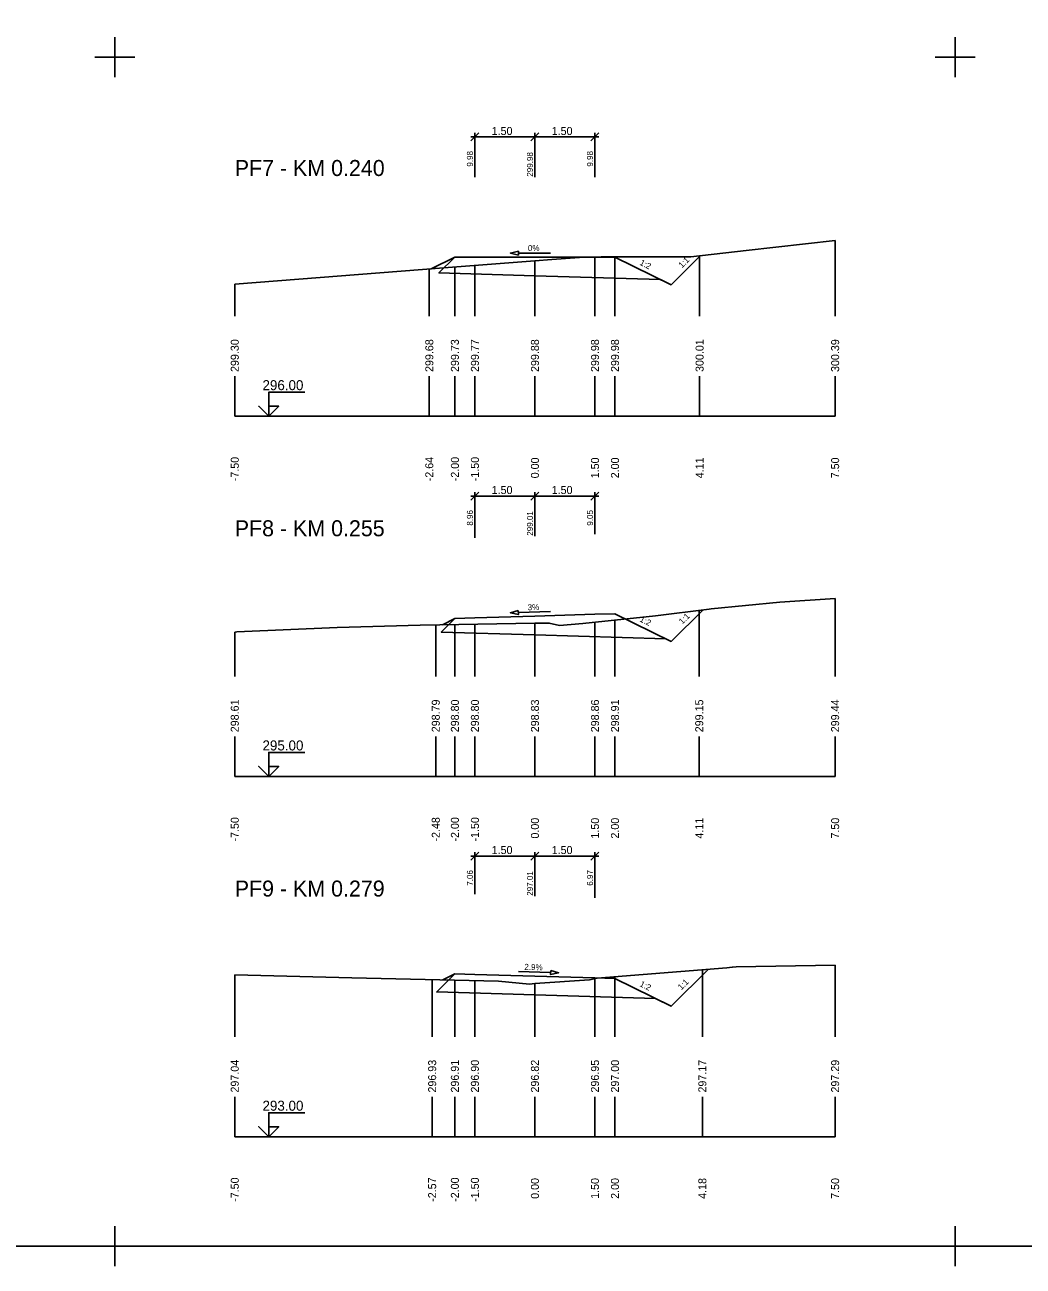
# Model space of a CAD drawing. Extents: x -5 to 1265, y -2 to 602.
# Drawn here: x 397.5 to 647, y -2.3 to 307.8 of the extents above; entities that cross this region are included whole.
import ezdxf

# ---------------------------------------------------------------- set-up
doc = ezdxf.new("R2010")
doc.units = 0
for name, color, linetype in [('KOTA', 7, 'Continuous'), ('KOTA_DELKY', 7, 'Continuous'), ('KOTA_DELKY_CONT', 7, 'Continuous'), ('NS_TELESO_VOZOVKY', 7, 'Continuous'), ('NS_V_PF', 7, 'Continuous'), ('REZY_PF_PUVODNI', 7, 'Continuous'), ('SESTAVY_REZU_PF', 7, 'Continuous'), ('SKLON', 7, 'Continuous'), ('SVK', 7, 'Continuous')]:
    doc.layers.add(name, color=color, linetype=linetype)

msp = doc.modelspace()

# ---------------------------------------------------------------- linework, layer by layer
for p, q in [((420, 304.67), (420, 294.67)), ((420, 304.67), (420, 294.67)), ((420, 304.67), (420, 294.67)), ((420, 304.67), (420, 294.67)), ((420, 304.67), (420, 294.67)), ((420, 304.67), (420, 294.67)), ((420, 304.67), (420, 294.67)), ((420, 304.67), (420, 294.67)), ((420, 304.67), (420, 294.67)), ((420, 304.67), (420, 294.67)), ((420, 304.67), (420, 294.67)), ((420, 304.67), (420, 294.67)), ((420, 304.67), (420, 294.67)), ((420, 304.67), (420, 294.67)), ((420, 304.67), (420, 294.67)), ((420, 304.67), (420, 294.67)), ((420, 304.67), (420, 294.67)), ((420, 304.67), (420, 294.67)), ((420, 304.67), (420, 294.67)), ((420, 304.67), (420, 294.67)), ((420, 304.67), (420, 294.67)), ((420, 304.67), (420, 294.67)), ((420, 304.67), (420, 294.67)), ((420, 304.67), (420, 294.67)), ((420, 304.67), (420, 294.67)), ((420, 304.67), (420, 294.67)), ((420, 304.67), (420, 294.67)), ((420, 304.67), (420, 294.67)), ((420, 304.67), (420, 294.67)), ((420, 304.67), (420, 294.67)), ((420, 304.67), (420, 294.67)), ((420, 304.67), (420, 294.67)), ((420, 304.67), (420, 294.67)), ((420, 304.67), (420, 294.67)), ((420, 304.67), (420, 294.67)), ((420, 304.67), (420, 294.67)), ((420, 304.67), (420, 294.67)), ((420, 304.67), (420, 294.67)), ((420, 304.67), (420, 294.67)), ((420, 304.67), (420, 294.67)), ((420, 304.67), (420, 294.67)), ((420, 304.67), (420, 294.67)), ((420, 304.67), (420, 294.67)), ((420, 304.67), (420, 294.67)), ((420, 304.67), (420, 294.67)), ((420, 304.67), (420, 294.67)), ((420, 304.67), (420, 294.67)), ((420, 304.67), (420, 294.67)), ((420, 304.67), (420, 294.67)), ((420, 304.67), (420, 294.67)), ((420, 304.67), (420, 294.67)), ((420, 304.67), (420, 294.67)), ((420, 304.67), (420, 294.67)), ((420, 304.67), (420, 294.67)), ((420, 304.67), (420, 294.67)), ((420, 304.67), (420, 294.67)), ((420, 304.67), (420, 294.67)), ((420, 304.67), (420, 294.67)), ((420, 304.67), (420, 294.67)), ((420, 304.67), (420, 294.67)), ((420, 304.67), (420, 294.67)), ((420, 304.67), (420, 294.67)), ((420, 304.67), (420, 294.67)), ((420, 304.67), (420, 294.67)), ((420, 304.67), (420, 294.67)), ((420, 304.67), (420, 294.67)), ((630, 304.67), (630, 294.67)), ((630, 304.67), (630, 294.67)), ((630, 304.67), (630, 294.67)), ((630, 304.67), (630, 294.67)), ((630, 304.67), (630, 294.67)), ((630, 304.67), (630, 294.67)), ((630, 304.67), (630, 294.67)), ((630, 304.67), (630, 294.67)), ((630, 304.67), (630, 294.67)), ((630, 304.67), (630, 294.67)), ((630, 304.67), (630, 294.67)), ((630, 304.67), (630, 294.67)), ((630, 304.67), (630, 294.67)), ((630, 304.67), (630, 294.67)), ((630, 304.67), (630, 294.67)), ((630, 304.67), (630, 294.67)), ((630, 304.67), (630, 294.67)), ((630, 304.67), (630, 294.67)), ((630, 304.67), (630, 294.67)), ((630, 304.67), (630, 294.67)), ((630, 304.67), (630, 294.67)), ((630, 304.67), (630, 294.67)), ((630, 304.67), (630, 294.67)), ((630, 304.67), (630, 294.67)), ((630, 304.67), (630, 294.67)), ((630, 304.67), (630, 294.67)), ((630, 304.67), (630, 294.67)), ((630, 304.67), (630, 294.67)), ((630, 304.67), (630, 294.67)), ((630, 304.67), (630, 294.67)), ((630, 304.67), (630, 294.67)), ((630, 304.67), (630, 294.67)), ((630, 304.67), (630, 294.67)), ((630, 304.67), (630, 294.67)), ((630, 304.67), (630, 294.67)), ((630, 304.67), (630, 294.67)), ((630, 304.67), (630, 294.67)), ((630, 304.67), (630, 294.67)), ((630, 304.67), (630, 294.67)), ((630, 304.67), (630, 294.67)), ((630, 304.67), (630, 294.67)), ((630, 304.67), (630, 294.67)), ((630, 304.67), (630, 294.67)), ((630, 304.67), (630, 294.67)), ((630, 304.67), (630, 294.67)), ((630, 304.67), (630, 294.67)), ((630, 304.67), (630, 294.67)), ((630, 304.67), (630, 294.67)), ((630, 304.67), (630, 294.67)), ((630, 304.67), (630, 294.67)), ((630, 304.67), (630, 294.67)), ((630, 304.67), (630, 294.67)), ((630, 304.67), (630, 294.67)), ((630, 304.67), (630, 294.67)), ((630, 304.67), (630, 294.67)), ((630, 304.67), (630, 294.67)), ((630, 304.67), (630, 294.67)), ((630, 304.67), (630, 294.67)), ((630, 304.67), (630, 294.67)), ((630, 304.67), (630, 294.67)), ((630, 304.67), (630, 294.67)), ((630, 304.67), (630, 294.67)), ((630, 304.67), (630, 294.67)), ((630, 304.67), (630, 294.67)), ((630, 304.67), (630, 294.67)), ((630, 304.67), (630, 294.67)), ((425, 299.67), (415, 299.67)), ((425, 299.67), (415, 299.67)), ((425, 299.67), (415, 299.67)), ((425, 299.67), (415, 299.67)), ((425, 299.67), (415, 299.67)), ((425, 299.67), (415, 299.67)), ((425, 299.67), (415, 299.67)), ((425, 299.67), (415, 299.67)), ((425, 299.67), (415, 299.67)), ((425, 299.67), (415, 299.67)), ((425, 299.67), (415, 299.67)), ((425, 299.67), (415, 299.67)), ((425, 299.67), (415, 299.67)), ((425, 299.67), (415, 299.67)), ((425, 299.67), (415, 299.67)), ((425, 299.67), (415, 299.67)), ((425, 299.67), (415, 299.67)), ((425, 299.67), (415, 299.67)), ((425, 299.67), (415, 299.67)), ((425, 299.67), (415, 299.67)), ((425, 299.67), (415, 299.67)), ((425, 299.67), (415, 299.67)), ((425, 299.67), (415, 299.67)), ((425, 299.67), (415, 299.67)), ((425, 299.67), (415, 299.67)), ((425, 299.67), (415, 299.67)), ((425, 299.67), (415, 299.67)), ((425, 299.67), (415, 299.67)), ((425, 299.67), (415, 299.67)), ((425, 299.67), (415, 299.67)), ((425, 299.67), (415, 299.67)), ((425, 299.67), (415, 299.67)), ((425, 299.67), (415, 299.67)), ((425, 299.67), (415, 299.67)), ((425, 299.67), (415, 299.67)), ((425, 299.67), (415, 299.67)), ((425, 299.67), (415, 299.67)), ((425, 299.67), (415, 299.67)), ((425, 299.67), (415, 299.67)), ((425, 299.67), (415, 299.67)), ((425, 299.67), (415, 299.67)), ((425, 299.67), (415, 299.67)), ((425, 299.67), (415, 299.67)), ((425, 299.67), (415, 299.67)), ((425, 299.67), (415, 299.67)), ((425, 299.67), (415, 299.67)), ((425, 299.67), (415, 299.67)), ((425, 299.67), (415, 299.67)), ((425, 299.67), (415, 299.67)), ((425, 299.67), (415, 299.67)), ((425, 299.67), (415, 299.67)), ((425, 299.67), (415, 299.67)), ((425, 299.67), (415, 299.67)), ((425, 299.67), (415, 299.67)), ((425, 299.67), (415, 299.67)), ((425, 299.67), (415, 299.67)), ((425, 299.67), (415, 299.67)), ((425, 299.67), (415, 299.67)), ((425, 299.67), (415, 299.67)), ((425, 299.67), (415, 299.67)), ((425, 299.67), (415, 299.67)), ((425, 299.67), (415, 299.67)), ((425, 299.67), (415, 299.67)), ((425, 299.67), (415, 299.67)), ((425, 299.67), (415, 299.67)), ((425, 299.67), (415, 299.67)), ((635, 299.67), (625, 299.67)), ((635, 299.67), (625, 299.67)), ((635, 299.67), (625, 299.67)), ((635, 299.67), (625, 299.67)), ((635, 299.67), (625, 299.67)), ((635, 299.67), (625, 299.67)), ((635, 299.67), (625, 299.67)), ((635, 299.67), (625, 299.67)), ((635, 299.67), (625, 299.67)), ((635, 299.67), (625, 299.67)), ((635, 299.67), (625, 299.67)), ((635, 299.67), (625, 299.67)), ((635, 299.67), (625, 299.67)), ((635, 299.67), (625, 299.67)), ((635, 299.67), (625, 299.67)), ((635, 299.67), (625, 299.67)), ((635, 299.67), (625, 299.67)), ((635, 299.67), (625, 299.67)), ((635, 299.67), (625, 299.67)), ((635, 299.67), (625, 299.67)), ((635, 299.67), (625, 299.67)), ((635, 299.67), (625, 299.67)), ((635, 299.67), (625, 299.67)), ((635, 299.67), (625, 299.67)), ((635, 299.67), (625, 299.67)), ((635, 299.67), (625, 299.67)), ((635, 299.67), (625, 299.67)), ((635, 299.67), (625, 299.67)), ((635, 299.67), (625, 299.67)), ((635, 299.67), (625, 299.67)), ((635, 299.67), (625, 299.67)), ((635, 299.67), (625, 299.67)), ((635, 299.67), (625, 299.67)), ((635, 299.67), (625, 299.67)), ((635, 299.67), (625, 299.67)), ((635, 299.67), (625, 299.67)), ((635, 299.67), (625, 299.67)), ((635, 299.67), (625, 299.67)), ((635, 299.67), (625, 299.67)), ((635, 299.67), (625, 299.67)), ((635, 299.67), (625, 299.67)), ((635, 299.67), (625, 299.67)), ((635, 299.67), (625, 299.67)), ((635, 299.67), (625, 299.67)), ((635, 299.67), (625, 299.67)), ((635, 299.67), (625, 299.67)), ((635, 299.67), (625, 299.67)), ((635, 299.67), (625, 299.67)), ((635, 299.67), (625, 299.67)), ((635, 299.67), (625, 299.67)), ((635, 299.67), (625, 299.67)), ((635, 299.67), (625, 299.67)), ((635, 299.67), (625, 299.67)), ((635, 299.67), (625, 299.67)), ((635, 299.67), (625, 299.67)), ((635, 299.67), (625, 299.67)), ((635, 299.67), (625, 299.67)), ((635, 299.67), (625, 299.67)), ((635, 299.67), (625, 299.67)), ((635, 299.67), (625, 299.67)), ((635, 299.67), (625, 299.67)), ((635, 299.67), (625, 299.67)), ((635, 299.67), (625, 299.67)), ((635, 299.67), (625, 299.67)), ((635, 299.67), (625, 299.67)), ((635, 299.67), (625, 299.67)), ((420, 7.67), (420, -2.33)), ((420, 7.67), (420, -2.33)), ((420, 7.67), (420, -2.33)), ((420, 7.67), (420, -2.33)), ((420, 7.67), (420, -2.33)), ((420, 7.67), (420, -2.33)), ((420, 7.67), (420, -2.33)), ((420, 7.67), (420, -2.33)), ((420, 7.67), (420, -2.33)), ((420, 7.67), (420, -2.33)), ((420, 7.67), (420, -2.33)), ((420, 7.67), (420, -2.33)), ((630, 7.67), (630, -2.33)), ((630, 7.67), (630, -2.33)), ((630, 7.67), (630, -2.33)), ((630, 7.67), (630, -2.33)), ((630, 7.67), (630, -2.33)), ((630, 7.67), (630, -2.33)), ((630, 7.67), (630, -2.33)), ((630, 7.67), (630, -2.33)), ((630, 7.67), (630, -2.33)), ((630, 7.67), (630, -2.33)), ((630, 7.67), (630, -2.33)), ((630, 7.67), (630, -2.33)), ((425, 2.67), (415, 2.67)), ((425, 2.67), (415, 2.67)), ((425, 2.67), (415, 2.67)), ((425, 2.67), (415, 2.67)), ((425, 2.67), (415, 2.67)), ((425, 2.67), (415, 2.67)), ((425, 2.67), (415, 2.67)), ((425, 2.67), (415, 2.67)), ((425, 2.67), (415, 2.67)), ((425, 2.67), (415, 2.67)), ((425, 2.67), (415, 2.67)), ((425, 2.67), (415, 2.67)), ((635, 2.67), (625, 2.67)), ((635, 2.67), (625, 2.67)), ((635, 2.67), (625, 2.67)), ((635, 2.67), (625, 2.67)), ((635, 2.67), (625, 2.67)), ((635, 2.67), (625, 2.67)), ((635, 2.67), (625, 2.67)), ((635, 2.67), (625, 2.67)), ((635, 2.67), (625, 2.67)), ((635, 2.67), (625, 2.67)), ((635, 2.67), (625, 2.67)), ((635, 2.67), (625, 2.67))]:
    msp.add_line(p, q)
msp.add_lwpolyline([(0, 596.67), (1260, 596.67), (1260, 2.67), (0, 2.67)], close=True)
at = {"layer": 'KOTA'}
for points in [[(458.51, 210), (456.01, 212.5), (458.51, 210), (458.51, 216), (467.51, 216)], [(458.51, 210), (461.01, 212.5), (458.51, 212.5), (458.51, 210)], [(458.51, 210), (461.01, 212.5), (458.51, 212.5)], [(458.51, 120), (456.01, 122.5), (458.51, 120), (458.51, 126), (467.51, 126)], [(458.51, 120), (461.01, 122.5), (458.51, 122.5), (458.51, 120)], [(458.51, 120), (461.01, 122.5), (458.51, 122.5)], [(458.51, 30), (456.01, 32.5), (458.51, 30), (458.51, 36), (467.51, 36)], [(458.51, 30), (461.01, 32.5), (458.51, 32.5), (458.51, 30)], [(458.51, 30), (461.01, 32.5), (458.51, 32.5)]]:
    msp.add_lwpolyline(points, dxfattribs=at)
at = {"layer": 'KOTA_DELKY'}
for points in [[(509, 278.75), (511, 280.75)], [(509, 279.75), (526, 279.75)], [(510, 269.75), (510, 280.75)], [(524, 278.75), (526, 280.75)], [(524, 278.75), (526, 280.75)], [(524, 279.75), (541, 279.75)], [(525, 269.75), (525, 280.75)], [(525, 269.75), (525, 280.75)], [(539, 278.75), (541, 280.75)], [(540, 269.75), (540, 280.75)], [(509, 189.06), (511, 191.06)], [(509, 190.06), (526, 190.06)], [(510, 179.61), (510, 191.06)], [(524, 189.06), (526, 191.06)], [(524, 189.06), (526, 191.06)], [(524, 190.06), (541, 190.06)], [(525, 180.06), (525, 191.06)], [(525, 180.06), (525, 191.06)], [(539, 189.06), (541, 191.06)], [(540, 180.51), (540, 191.06)], [(509, 99.12), (511, 101.12)], [(509, 100.12), (526, 100.12)], [(510, 90.57), (510, 101.12)], [(524, 99.12), (526, 101.12)], [(524, 99.12), (526, 101.12)], [(524, 100.12), (541, 100.12)], [(525, 90.12), (525, 101.12)], [(525, 90.12), (525, 101.12)], [(539, 99.12), (541, 101.12)], [(540, 89.68), (540, 101.12)]]:
    msp.add_lwpolyline(points, dxfattribs=at)
at = {"layer": 'NS_TELESO_VOZOVKY'}
for points in [[(525, 249.75), (540, 249.75), (545, 249.75), (559.01, 242.82), (556.41, 244.11), (525, 245.05), (501.02, 245.77), (505, 249.75), (510, 249.75), (525, 249.75)], [(525, 160.06), (540, 160.51), (545, 160.66), (559.01, 153.73), (557.7, 154.38), (525, 155.36), (501.6, 156.06), (505, 159.46), (510, 159.61), (525, 160.06)], [(525, 70.12), (540, 69.68), (545, 69.54), (559.01, 62.61), (555.14, 64.52), (525, 65.42), (500.45, 66.16), (505, 70.71), (510, 70.57), (525, 70.12)]]:
    msp.add_lwpolyline(points, dxfattribs=at)
at = {"layer": 'NS_V_PF'}
for points in [[(499.1, 246.8), (505, 249.75), (510, 249.75), (525, 249.75), (540, 249.75), (545, 249.75), (559.01, 242.82), (566.37, 250.11)], [(501.91, 157.92), (505, 159.46), (510, 159.61), (525, 160.06), (540, 160.51), (545, 160.66), (559.01, 153.73), (566.99, 161.63)], [(501.95, 69.19), (505, 70.71), (510, 70.57), (525, 70.12), (540, 69.68), (545, 69.54), (559.01, 62.61), (568.35, 71.85)]]:
    msp.add_lwpolyline(points, dxfattribs=at)
at = {"layer": 'REZY_PF_PUVODNI'}
for points in [[(450, 242.96), (502.25, 247.05), (525, 248.83), (525, 248.83), (529.2, 249.16), (536.16, 249.64), (541.58, 249.84), (563.94, 249.83), (577.8, 251.4), (600, 253.9)], [(450, 156.08), (450.55, 156.09), (475.56, 157.2), (496.3, 157.77), (501.21, 157.91), (525, 158.26), (528.59, 158.32), (531.17, 157.75), (536.95, 158.23), (555.13, 160.15), (568.5, 161.81), (569.03, 161.88), (586.15, 163.55), (600, 164.44)], [(450, 70.42), (479.27, 69.73), (515.86, 68.86), (523.66, 68.15), (525, 68.25), (525, 68.25), (538.66, 69.23), (540.56, 69.62), (572.92, 72.22), (574.24, 72.39), (574.4, 72.4), (575.24, 72.45), (600, 72.9)]]:
    msp.add_lwpolyline(points, dxfattribs=at)
at = {"layer": 'SESTAVY_REZU_PF'}
for points in [[(450, 210), (600, 210)], [(450, 120), (600, 120)], [(450, 30), (600, 30)]]:
    msp.add_lwpolyline(points, dxfattribs=at)
at = {"layer": 'SKLON'}
for points in [[(520.88, 251.25), (518.88, 250.75), (520.88, 250.25), (520.88, 251.25)], [(520.88, 250.75), (528.88, 250.75)], [(520.84, 161.44), (518.86, 160.88), (520.87, 160.44), (520.84, 161.44)], [(520.86, 160.94), (528.85, 161.18)], [(528.93, 71.51), (530.91, 70.95), (528.9, 70.51), (528.93, 71.51)], [(520.92, 71.25), (528.91, 71.01)]]:
    msp.add_lwpolyline(points, dxfattribs=at)
for points in [[(520.88, 251.25), (518.88, 250.75), (520.88, 250.25)], [(520.84, 161.44), (518.86, 160.88), (520.87, 160.44)], [(528.93, 71.51), (530.91, 70.95), (528.9, 70.51)]]:
    msp.add_lwpolyline(points, close=True, dxfattribs=at)
at = {"layer": 'SVK'}
for points in [[(600, 235), (600, 253.9)], [(525, 235), (525, 248.83)], [(540, 235), (540, 249.79)], [(545, 235), (545, 249.84)], [(566.14, 235), (566.14, 250.08)], [(498.61, 235), (498.61, 246.76)], [(505, 235), (505, 247.26)], [(510, 235), (510, 247.65)], [(450, 235), (450, 242.96)], [(450, 210), (450, 220)], [(498.61, 210), (498.61, 220)], [(505, 210), (505, 220)], [(510, 210), (510, 220)], [(525, 210), (525, 220)], [(540, 210), (540, 220)], [(545, 210), (545, 220)], [(566.14, 210), (566.14, 220)], [(600, 210), (600, 220)], [(600, 145), (600, 164.44)], [(566.05, 145), (566.05, 161.51)], [(525, 145), (525, 158.26)], [(540, 145), (540, 158.55)], [(545, 145), (545, 159.08)], [(450, 145), (450, 156.08)], [(500.22, 145), (500.22, 157.88)], [(505, 145), (505, 157.96)], [(510, 145), (510, 158.04)], [(450, 120), (450, 130)], [(500.22, 120), (500.22, 130)], [(505, 120), (505, 130)], [(510, 120), (510, 130)], [(525, 120), (525, 130)], [(540, 120), (540, 130)], [(545, 120), (545, 130)], [(566.05, 120), (566.05, 130)], [(600, 120), (600, 130)], [(566.83, 55), (566.83, 71.73)], [(600, 55), (600, 72.9)], [(450, 55), (450, 70.42)], [(499.32, 55), (499.32, 69.25)], [(505, 55), (505, 69.12)], [(510, 55), (510, 69)], [(525, 55), (525, 68.25)], [(540, 55), (540, 69.51)], [(545, 55), (545, 69.98)], [(450, 30), (450, 40)], [(499.32, 30), (499.32, 40)], [(505, 30), (505, 40)], [(510, 30), (510, 40)], [(525, 30), (525, 40)], [(540, 30), (540, 40)], [(545, 30), (545, 40)], [(566.83, 30), (566.83, 40)], [(600, 30), (600, 40)]]:
    msp.add_lwpolyline(points, dxfattribs=at)

# ---------------------------------------------------------------- texts
at = {"layer": 'KOTA'}
for s, p in [('296.00', (456.93, 216.5)), ('295.00', (456.93, 126.5)), ('293.00', (456.93, 36.5))]:
    msp.add_text(s, height=2.5, dxfattribs=at).set_placement(p)
at = {"layer": 'KOTA_DELKY'}
for p in [(514.19, 280.25), (529.19, 280.25), (514.19, 190.56), (529.19, 190.56), (514.19, 100.62), (529.19, 100.62)]:
    msp.add_text('1.50', height=2, dxfattribs=at).set_placement(p)
at = {"layer": 'KOTA_DELKY_CONT'}
for s, p in [('9.98', (509.5, 272.34)), ('9.98', (539.5, 272.34)), ('299.98', (524.5, 269.83)), ('8.96', (509.5, 182.65)), ('299.01', (524.5, 180.14)), ('9.05', (539.5, 182.65)), ('7.06', (509.5, 92.71)), ('297.01', (524.5, 90.2)), ('6.97', (539.5, 92.71))]:
    msp.add_text(s, height=1.5, rotation=90, dxfattribs=at).set_placement(p)
at = {"layer": 'SESTAVY_REZU_PF'}
for s, p in [('PF7 - KM 0.240', (450, 270)), ('PF8 - KM 0.255', (450, 180)), ('PF9 - KM 0.279', (450, 90))]:
    msp.add_text(s, height=4, dxfattribs=at).set_placement(p)
at = {"layer": 'SKLON'}
for s, rotation, p in [('0%', 0.0036, (523.24, 251.25)), ('1:2', 333.679, (551.04, 247.88)), ('1:1', 44.7149, (561.74, 246.93)), ('3%', 1.7184, (523.2, 161.51)), ('1:2', 333.679, (551.04, 158.79)), ('1:1', 44.7149, (561.83, 157.93)), ('2.9%', 358.3157, (522.34, 71.7)), ('1:2', 333.679, (551.04, 67.67)), ('1:1', 44.7149, (561.58, 66.56))]:
    msp.add_text(s, height=1.5, rotation=rotation, dxfattribs=at).set_placement(p)
at = {"layer": 'SVK'}
for s, p in [(' 299.30', (451, 220.3)), (' 299.68', (499.61, 220.3)), (' 299.73', (506, 220.3)), (' 299.77', (511, 220.3)), (' 299.88', (526, 220.3)), (' 299.98', (541, 220.3)), (' 299.98', (546, 220.3)), (' 300.01', (567.14, 220.3)), (' 300.39', (601, 220.3)), (' -7.50', (451, 193)), (' -2.64', (499.61, 193)), (' -2.00', (506, 193)), (' -1.50', (511, 193)), ('  0.00', (526, 193)), ('  1.50', (541, 193)), ('  2.00', (546, 193)), ('  4.11', (567.14, 193)), ('  7.50', (601, 193)), (' 298.61', (451, 130.3)), (' 298.79', (501.22, 130.3)), (' 298.80', (506, 130.3)), (' 298.80', (511, 130.3)), (' 298.83', (526, 130.3)), (' 298.86', (541, 130.3)), (' 298.91', (546, 130.3)), (' 299.15', (567.05, 130.3)), (' 299.44', (601, 130.3)), (' -7.50', (451, 103)), (' -2.48', (501.22, 103)), (' -2.00', (506, 103)), (' -1.50', (511, 103)), ('  0.00', (526, 103)), ('  1.50', (541, 103)), ('  2.00', (546, 103)), ('  4.11', (567.05, 103)), ('  7.50', (601, 103)), (' 297.04', (451, 40.3)), (' 296.93', (500.32, 40.3)), (' 296.91', (506, 40.3)), (' 296.90', (511, 40.3)), (' 296.82', (526, 40.3)), (' 296.95', (541, 40.3)), (' 297.00', (546, 40.3)), (' 297.17', (567.83, 40.3)), (' 297.29', (601, 40.3)), (' -7.50', (451, 13)), (' -2.57', (500.32, 13)), (' -2.00', (506, 13)), (' -1.50', (511, 13)), ('  0.00', (526, 13)), ('  1.50', (541, 13)), ('  2.00', (546, 13)), ('  4.18', (567.83, 13)), ('  7.50', (601, 13))]:
    msp.add_text(s, height=2, rotation=90, dxfattribs=at).set_placement(p)

doc.saveas('drawing.dxf')
